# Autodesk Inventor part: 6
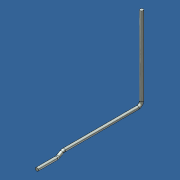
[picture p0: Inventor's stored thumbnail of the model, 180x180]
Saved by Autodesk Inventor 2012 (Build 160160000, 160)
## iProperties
Created: 2013-04
Part Number: 6
Material: Steel
Document SubType Name: Modeling
Designer: Admin
Density: 7.85 g/cm^3
Mass: 23.3594 g
Surface Area: 30.0085 cm^2
Volume: 2.97572 cm^3
Author: Admin
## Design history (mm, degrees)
node "61"
node "6"
node "Base1"
